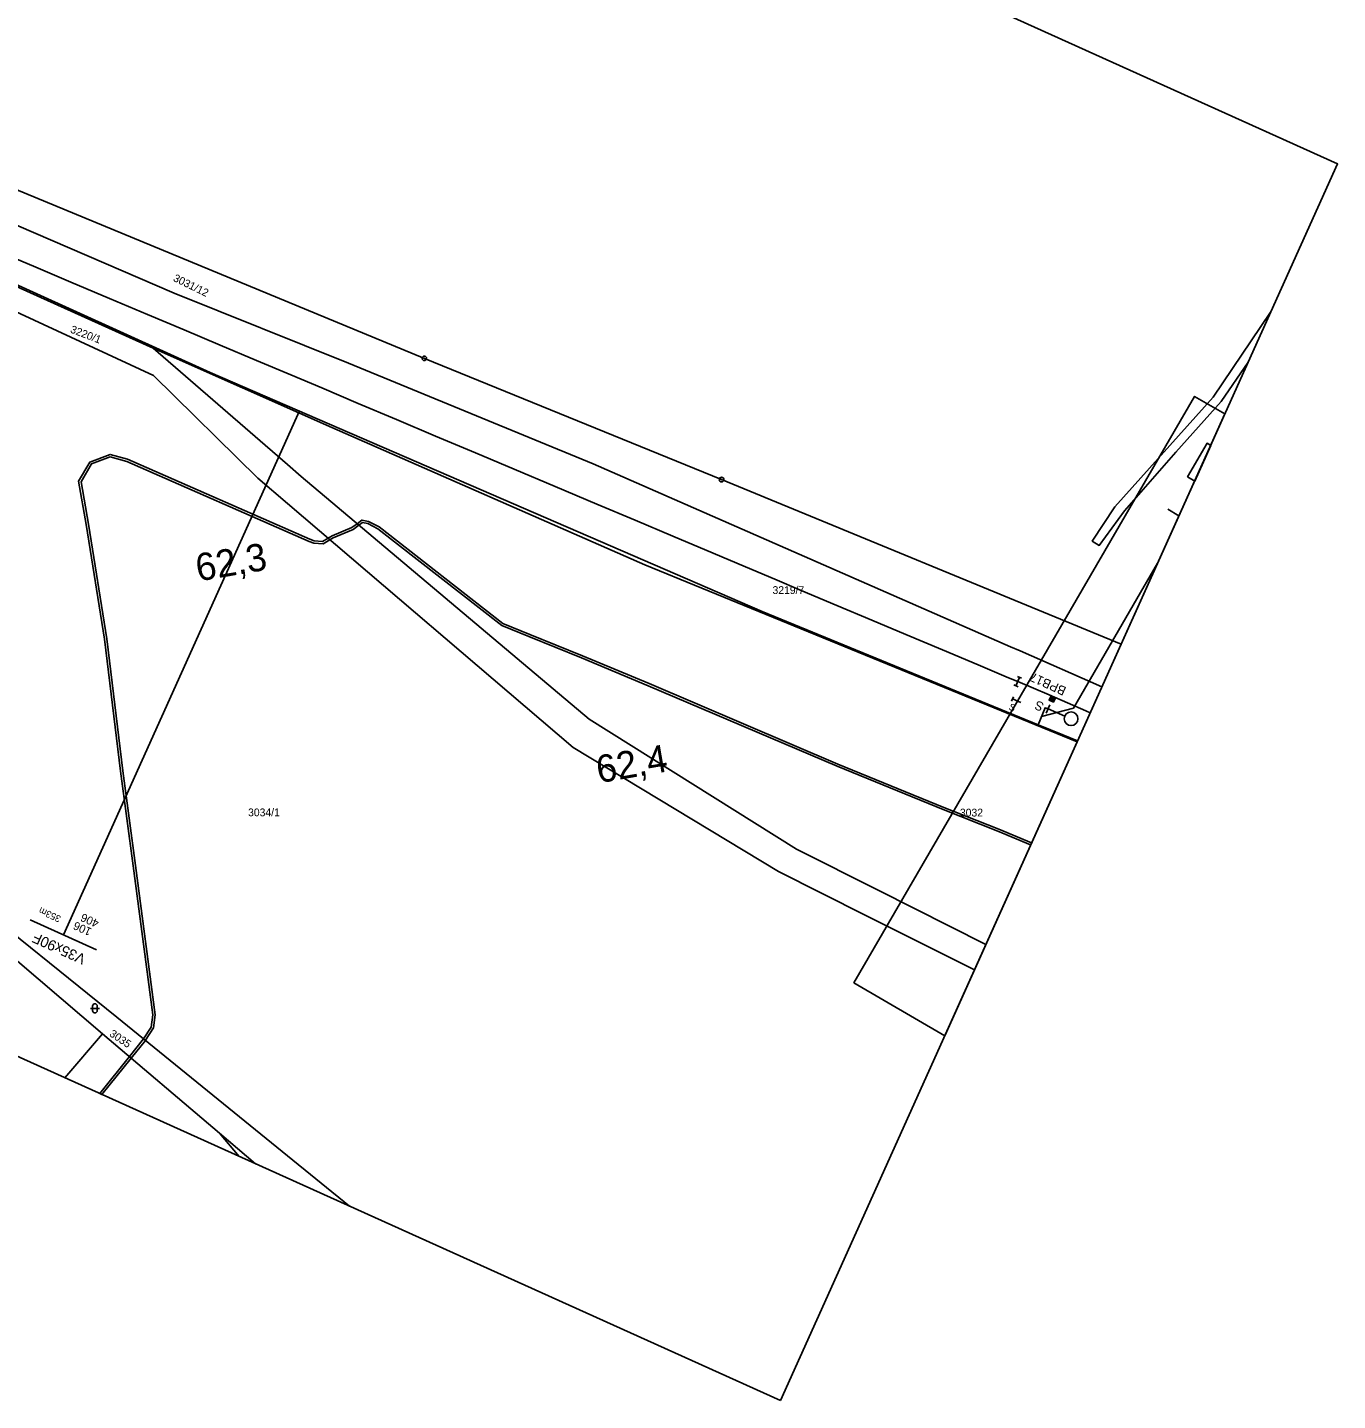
# Model space of a CAD drawing. Extents: x -621716 to -621020, y -1122350 to -1121821.
# Drawn here: x -621307 to -621020, y -1122350.4 to -1122049.8 of the extents above; entities that cross this region are included whole.
import ezdxf

# ---------------------------------------------------------------- set-up
doc = ezdxf.new("R2010")
doc.units = 0
for name, color, linetype in [('hm', 7, 'Continuous'), ('HranDP', 7, 'Continuous'), ('Hranice parcel', 7, 'Continuous'), ('Parcelní čísla', 7, 'Continuous'), ('Razítka', 7, 'Continuous'), ('Rámečky-tisk', 7, 'Continuous'), ('STANICENI NOVE HM', 7, 'Continuous'), ('Vrstva 1', 7, 'Continuous'), ('Vrstva 2', 7, 'Continuous'), ('Vrstva 3', 7, 'Continuous'), ('Vrstva 33', 7, 'Continuous'), ('Vrstva 6', 7, 'Continuous'), ('Věcná břemena k části', 7, 'Continuous'), ('Značky bodu BP', 7, 'Continuous'), ('Značky kultur', 7, 'Continuous')]:
    doc.layers.add(name, color=color, linetype=linetype)

msp = doc.modelspace()

# ---------------------------------------------------------------- linework, layer by layer
at = {"layer": 'hm'}
for p, q in [((-621236.12, -1122131.3), (-621236.12, -1122131.3)), ((-621143.95, -1122170.24), (-621143.95, -1122170.24))]:
    msp.add_line(p, q, dxfattribs=at)
at = {"layer": 'HranDP'}
msp.add_line((-621240.3, -1122137.45), (-621279.41, -1122120.03), dxfattribs=at)
for points in [[(-621236.6, -1122123.3), (-621274.82, -1122107.97), (-621397.6, -1122055.13)], [(-621415.82, -1122061.13), (-621412.83, -1122062.84), (-621404.9, -1122067.41), (-621374.43, -1122078.72), (-621360.65, -1122083.94), (-621354.93, -1122086.03), (-621279.41, -1122120.03)], [(-621071.57, -1122194.18), (-621089.46, -1122186.34), (-621091.58, -1122185.41), (-621183.06, -1122145.34), (-621236.6, -1122123.3)], [(-621077.02, -1122206.26), (-621096.79, -1122198.16), (-621171.69, -1122167.46), (-621240.3, -1122137.45)]]:
    msp.add_lwpolyline(points, dxfattribs=at)
at = {"layer": 'Hranice parcel'}
for p, q in [((-621240.3, -1122137.45), (-621279.41, -1122120.03)), ((-621323.04, -1122242.46), (-621290.49, -1122270.16)), ((-621323.04, -1122242.46), (-621290.49, -1122270.16)), ((-621290.49, -1122270.16), (-621264.88, -1122291.93)), ((-621290.49, -1122270.16), (-621264.88, -1122291.93)), ((-621264.88, -1122291.93), (-621257.02, -1122298.61)), ((-621264.88, -1122291.93), (-621257.02, -1122298.61))]:
    msp.add_line(p, q, dxfattribs=at)
for points in [[(-621316.28, -1121963.73), (-621318.05, -1121968.15), (-621373.38, -1122024.18), (-621378.72, -1122030.05), (-621381.72, -1122035.12), (-621383.2, -1122041.04), (-621383.06, -1122046.37), (-621381.45, -1122051.28), (-621377.34, -1122056.11), (-621371.25, -1122059.79), (-621220, -1122122.28), (-621154.89, -1122148.82), (-621067.38, -1122184.88)], [(-621236.6, -1122123.3), (-621274.82, -1122107.97), (-621397.6, -1122055.13)], [(-621415.82, -1122061.13), (-621412.83, -1122062.84), (-621404.9, -1122067.41), (-621374.43, -1122078.72), (-621360.65, -1122083.94), (-621354.93, -1122086.03), (-621279.41, -1122120.03)], [(-621187.4, -1122207.5), (-621250, -1122154.05), (-621256.5, -1122148.5), (-621279.33, -1122126.02), (-621347.74, -1122094.36), (-621373.17, -1122084.12), (-621407.84, -1122078), (-621413.72, -1122077.04), (-621414.64, -1122076.64)], [(-621236.42, -1122307.9), (-621250, -1122296.86), (-621287.36, -1122266.52), (-621321.13, -1122239.4), (-621337.07, -1122226.87), (-621346.7, -1122218.55), (-621364.2, -1122203.4), (-621376.27, -1122193.53), (-621383.11, -1122186.25), (-621403.55, -1122154.5), (-621447.98, -1122102.71)], [(-621039.54, -1122123.11), (-621045.46, -1122131.72), (-621055.41, -1122142.78), (-621066.65, -1122155.68), (-621072.18, -1122163.23), (-621073.7, -1122162.28), (-621068.77, -1122154.75), (-621047.24, -1122130.75), (-621034.62, -1122112.2)], [(-621279.41, -1122120.03), (-621250, -1122145.55), (-621247, -1122148.15)], [(-621071.57, -1122194.18), (-621089.46, -1122186.34), (-621091.58, -1122185.41), (-621183.06, -1122145.34), (-621236.6, -1122123.3)], [(-621077.02, -1122206.26), (-621096.79, -1122198.16), (-621171.69, -1122167.46), (-621240.3, -1122137.45)], [(-621247, -1122148.15), (-621183.91, -1122201.29), (-621138.49, -1122229.74), (-621120.6, -1122238.74), (-621097.01, -1122250.61)], [(-621099.51, -1122256.14), (-621123.45, -1122244.15), (-621142.42, -1122234.65), (-621187.4, -1122207.5)], [(-621298.77, -1122279.79), (-621290.49, -1122270.16)], [(-621264.88, -1122291.93), (-621260.6, -1122296.99)]]:
    msp.add_lwpolyline(points, dxfattribs=at)
at = {"layer": 'Razítka'}
msp.add_line((-621051.26, -1122149.13), (-621047.75, -1122141.34), dxfattribs=at)
msp.add_lwpolyline([(-621047.75, -1122141.34), (-621048.56, -1122140.87), (-621052.83, -1122148.21), (-621051.26, -1122149.13)], dxfattribs=at)
at = {"layer": 'Rámečky-tisk'}
msp.add_line((-621106.01, -1122270.57), (-621044.65, -1122134.46), dxfattribs=at)
for points in [[(-621594.3, -1121820.78), (-621716.36, -1122091.54), (-621142.02, -1122350.45)], [(-621142.02, -1122350.45), (-621019.96, -1122079.69), (-621594.3, -1121820.78)], [(-621044.65, -1122134.46), (-621051.28, -1122130.61), (-621125.92, -1122258.99), (-621106.01, -1122270.57)]]:
    msp.add_lwpolyline(points, dxfattribs=at)
at = {"layer": 'Vrstva 1'}
for points in [[(-621085.52, -1122202.49), (-621145.97, -1122177.73), (-621266.9, -1122125.34), (-621335.07, -1122094.53), (-621348.64, -1122088.4), (-621357.58, -1122084.62), (-621357.08, -1122083.45), (-621364.5, -1122080.32), (-621400.77, -1122065), (-621401.81, -1122066.92), (-621406.73, -1122065.04)], [(-621313.5, -1122098.8), (-621305.66, -1122102.11), (-621297.43, -1122105.59), (-621288.95, -1122109.16), (-621280.64, -1122112.66), (-621272.65, -1122116.04), (-621264.7, -1122119.38), (-621256.74, -1122122.74), (-621249.24, -1122125.9), (-621242.46, -1122128.76), (-621234.48, -1122132.13), (-621226.13, -1122135.65), (-621217.53, -1122139.28), (-621208.79, -1122142.96), (-621200.3, -1122146.55), (-621191.38, -1122150.31), (-621182.22, -1122154.18), (-621173.81, -1122157.72), (-621165.57, -1122161.19), (-621156.77, -1122164.91), (-621149.67, -1122167.91), (-621143.22, -1122170.63), (-621137.43, -1122173.08), (-621129.68, -1122176.35), (-621122.01, -1122179.58), (-621114.57, -1122182.71), (-621106.5, -1122186.11), (-621098.7, -1122189.4), (-621092.01, -1122192.21), (-621090.02, -1122193.05), (-621083.15, -1122195.96), (-621075.1, -1122199.44), (-621074.14, -1122199.87)], [(-621083.39, -1122199.04), (-621084.03, -1122198.76), (-621085.52, -1122202.49)], [(-621076.91, -1122206.02), (-621080.17, -1122204.68), (-621085.52, -1122202.49)]]:
    msp.add_lwpolyline(points, dxfattribs=at)
at = {"layer": 'Vrstva 2'}
for p, q in [((-621083.12, -1122197.06), (-621081.8, -1122196.57)), ((-621083.04, -1122196.89), (-621081.97, -1122196.5)), ((-621083.03, -1122197.16), (-621081.8, -1122196.71)), ((-621082.96, -1122196.72), (-621082.14, -1122196.42)), ((-621082.88, -1122196.55), (-621082.31, -1122196.34)), ((-621082.86, -1122197.24), (-621081.88, -1122196.88)), ((-621082.8, -1122196.38), (-621082.48, -1122196.26)), ((-621082.73, -1122196.21), (-621082.65, -1122196.19)), ((-621082.69, -1122197.32), (-621081.96, -1122197.05)), ((-621082.52, -1122197.4), (-621082.03, -1122197.22)), ((-621083, -1122198.12), (-621083.78, -1122199.96)), ((-621079.7, -1122200.6), (-621083.39, -1122199.04)), ((-621082.36, -1122197.48), (-621082.11, -1122197.39))]:
    msp.add_line(p, q, dxfattribs=at)
msp.add_lwpolyline([(-621082.7, -1122196.16), (-621081.75, -1122196.6), (-621082.19, -1122197.55), (-621083.14, -1122197.11)], close=True, dxfattribs=at)
msp.add_lwpolyline([(-621082.7, -1122196.16), (-621081.75, -1122196.6), (-621082.19, -1122197.55), (-621083.14, -1122197.11)], close=True, dxfattribs=at)
msp.add_circle((-621078.32, -1122201.18), 1.5, dxfattribs=at)
at = {"layer": 'Vrstva 3'}
for p, q in [((-621090.87, -1122193.78), (-621089.95, -1122194.16)), ((-621089.64, -1122192.13), (-621090.41, -1122193.97)), ((-621090.1, -1122191.93), (-621089.18, -1122192.32))]:
    msp.add_line(p, q, dxfattribs=at)
at = {"layer": 'Vrstva 33'}
for p, q in [((-621247.39, -1122133.79), (-621299.08, -1122248.46)), ((-621057.15, -1122155.33), (-621054.7, -1122156.76)), ((-621077.82, -1122198.83), (-621059.37, -1122167.11)), ((-621084.79, -1122200.68), (-621077.82, -1122198.83)), ((-621306.38, -1122245.17), (-621291.79, -1122251.75))]:
    msp.add_line(p, q, dxfattribs=at)
at = {"layer": 'Vrstva 6'}
for p, q in [((-621090.97, -1122196.38), (-621091.37, -1122197.3)), ((-621089.36, -1122197.63), (-621091.17, -1122196.84))]:
    msp.add_line(p, q, dxfattribs=at)
at = {"layer": 'Věcná břemena k části'}
for p, q in [((-621087.19, -1122228.82), (-621086.99, -1122228.37)), ((-621291.09, -1122283.25), (-621290.63, -1122283.46))]:
    msp.add_line(p, q, dxfattribs=at)
for points in [[(-621242.32, -1122162.36), (-621244.11, -1122162.22), (-621245.08, -1122161.9), (-621285.04, -1122144.35), (-621288.86, -1122143.32), (-621293.29, -1122145), (-621295.74, -1122149.19), (-621294.06, -1122158.66), (-621290.04, -1122183.78), (-621286.56, -1122212.67), (-621283.77, -1122233.35), (-621279.5, -1122265.97), (-621279.82, -1122268.68), (-621281.5, -1122271.28), (-621281.11, -1122271.59), (-621281.1, -1122271.58), (-621279.34, -1122268.86), (-621279, -1122265.97), (-621283.27, -1122233.29), (-621286.06, -1122212.61), (-621289.54, -1122183.72), (-621293.56, -1122158.58), (-621295.22, -1122149.29), (-621292.95, -1122145.4), (-621288.84, -1122143.84), (-621285.2, -1122144.83), (-621245.26, -1122162.36), (-621244.21, -1122162.72), (-621242.2, -1122162.86), (-621240.68, -1122162.01), (-621241.08, -1122161.66)], [(-621234.35, -1122158.81), (-621234.74, -1122158.48), (-621235.87, -1122159.33), (-621240.17, -1122161.16), (-621241.08, -1122161.66), (-621240.68, -1122162.01), (-621239.95, -1122161.6), (-621235.61, -1122159.77)], [(-621281.11, -1122271.59), (-621281.5, -1122271.28), (-621284.61, -1122275.16), (-621284.23, -1122275.48)]]:
    msp.add_lwpolyline(points, close=True, dxfattribs=at)
for points in [[(-621086.99, -1122228.37), (-621094.18, -1122225.34), (-621106.18, -1122220.59), (-621129.4, -1122211.1), (-621170.76, -1122193.49), (-621185.38, -1122187.37), (-621196.91, -1122182.72), (-621202.81, -1122180.31), (-621229.89, -1122159.2), (-621232.24, -1122157.96), (-621233.68, -1122157.67), (-621234.74, -1122158.48), (-621234.35, -1122158.81), (-621233.56, -1122158.21), (-621232.4, -1122158.44), (-621230.17, -1122159.62), (-621203.07, -1122180.75), (-621197.09, -1122183.18), (-621185.58, -1122187.83), (-621170.96, -1122193.95), (-621129.6, -1122211.56), (-621106.36, -1122221.05), (-621094.36, -1122225.8), (-621087.19, -1122228.82)], [(-621290.63, -1122283.46), (-621284.23, -1122275.48), (-621284.61, -1122275.16), (-621291.09, -1122283.25)]]:
    msp.add_lwpolyline(points, dxfattribs=at)
at = {"layer": 'Značky bodu BP'}
for centre, radius in [((-621220, -1122122.28), 0.5), ((-621220, -1122122.28), 0.0303), ((-621154.89, -1122148.82), 0.5), ((-621154.89, -1122148.82), 0.0303)]:
    msp.add_circle(centre, radius, dxfattribs=at)
at = {"layer": 'Značky kultur'}
for p, q in [((-621293.17, -1122264.59), (-621291.17, -1122264.59)), ((-621292.67, -1122264.09), (-621292.67, -1122265.09)), ((-621291.67, -1122265.09), (-621291.67, -1122264.09))]:
    msp.add_line(p, q, dxfattribs=at)
for centre, start, end in [((-621292.17, -1122264.09), 0, 180), ((-621292.17, -1122265.09), 180, 359.9879)]:
    msp.add_arc(centre, 0.5, start, end, dxfattribs=at)

# ---------------------------------------------------------------- texts
at = {"layer": 'Parcelní čísla'}
for s, rotation, p in [('3031/12', 334, (-621275.18, -1122105.26)), ('3220/1', 339, (-621297.7, -1122116.58)), ('3035', 326, (-621289.15, -1122270.52))]:
    msp.add_text(s, height=1.7, rotation=rotation, dxfattribs=at).set_placement(p)
for s, p in [('3219/7', (-621143.74, -1122173.86)), ('3034/1', (-621258.62, -1122222.53)), ('3032', (-621102.69, -1122222.58))]:
    msp.add_text(s, height=1.7, dxfattribs=at).set_placement(p)
at = {"layer": 'STANICENI NOVE HM'}
for s, p in [('62,3', (-621269.56, -1122171.14)), ('62,4', (-621181.81, -1122215.31))]:
    msp.add_text(s, height=6, rotation=9.6991, dxfattribs=at).set_placement(p)
at = {"layer": 'Vrstva 3'}
for s, p in [('BPB17', (-621079.23, -1122194.37)), ('S', (-621084.1, -1122197.86))]:
    msp.add_text(s, height=2, rotation=155.7341, dxfattribs=at).set_placement(p)
at = {"layer": 'Vrstva 33'}
for s, height, p in [('353m', 1.5, (-621299.47, -1122244.45)), ('406', 1.8, (-621291.11, -1122245.36)), ('V35x90F', 2.3, (-621293.97, -1122252.96)), ('106', 1.8, (-621292.72, -1122247.16))]:
    msp.add_text(s, height=height, rotation=155.7341, dxfattribs=at).set_placement(p)
at = {"layer": 'Vrstva 6'}
msp.add_text('S', height=1.5, rotation=336.4373, dxfattribs=at).set_placement((-621092.12, -1122199.11))

doc.saveas('drawing.dxf')
